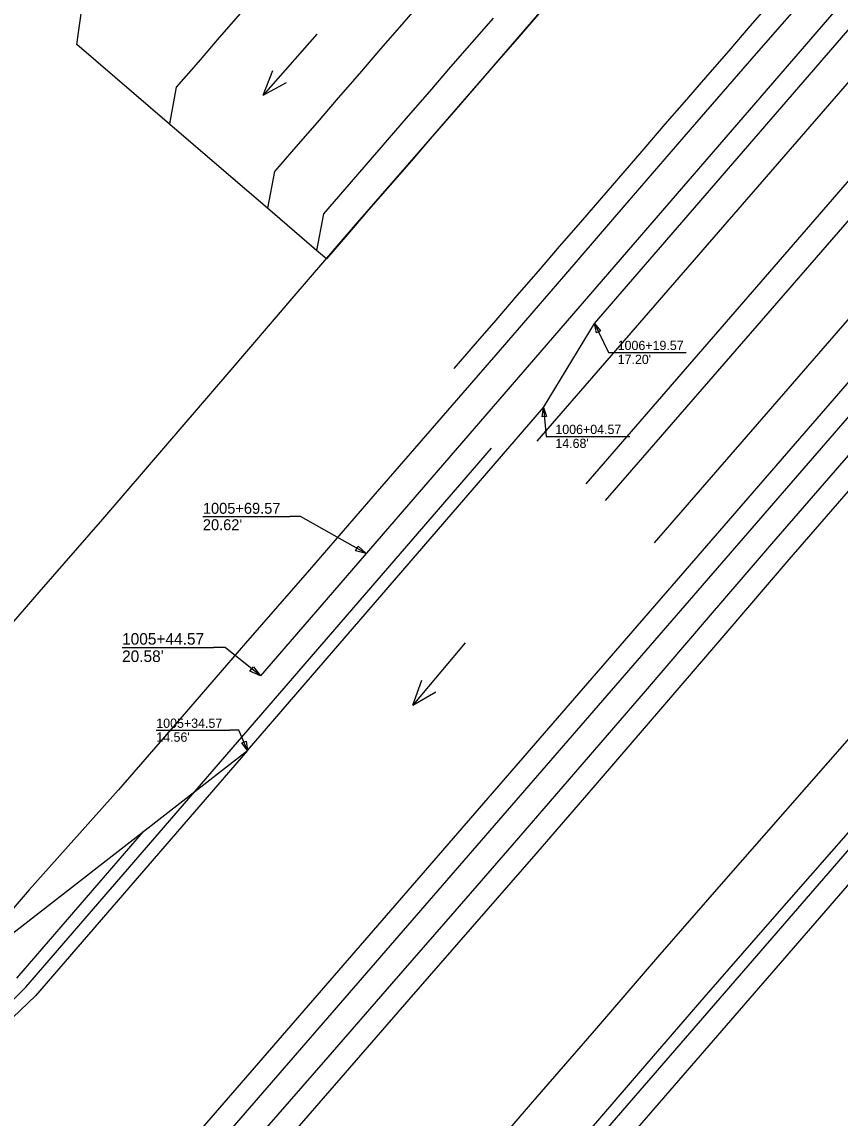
# Model space of a CAD drawing. Extents: x 1006695 to 1009377, y 1883329 to 1886115.
# Drawn here: x 1007700.6 to 1007827, y 1884510 to 1884679.4 of the extents above; entities that cross this region are included whole.
import ezdxf

# ---------------------------------------------------------------- set-up
doc = ezdxf.new("R2010")
doc.units = 0
for name, color, linetype in [('R_Drainage Concrete Lining I-30', 7, 'Continuous'), ('R_I-30 Information', 7, 'Continuous'), ('R_No Plot', 7, 'Continuous'), ('R_Prop EOL', 7, 'Continuous'), ('R_Prop EOS I-30', 7, 'Continuous'), ('R_Prop Fence', 7, 'Continuous'), ('R_Prop I-30 Guardrail', 7, 'Continuous'), ('R_Water Annot', 7, 'Continuous')]:
    doc.layers.add(name, color=color, linetype=linetype)

msp = doc.modelspace()

# ---------------------------------------------------------------- linework, layer by layer
at = {"layer": 'R_Drainage Concrete Lining I-30'}
for p, q in [((1007735.45, 1884566.81), (1007702.68, 1884528.85)), ((1007719.32, 1884554.25), (1007699.75, 1884531.58)), ((1007702.68, 1884528.85), (1007666.48, 1884494.25))]:
    msp.add_line(p, q, dxfattribs=at)
at = {"layer": 'R_I-30 Information'}
for p, q in [((1007780.22, 1884614.59), (1007976.64, 1884841.35)), ((1007787.78, 1884608.04), (1007984.2, 1884834.8)), ((1007790.8, 1884605.42), (1007987.22, 1884832.18)), ((1007798.36, 1884598.88), (1007994.78, 1884825.63))]:
    msp.add_line(p, q, dxfattribs=at)
for points in [[(1007740.78, 1884505.63), (1007750.62, 1884516.95), (1007760.46, 1884528.27), (1007770.23, 1884539.51), (1007780.07, 1884550.83), (1007789.88, 1884562.17), (1007799.65, 1884573.56), (1007809.41, 1884584.94), (1007819.18, 1884596.32), (1007829.02, 1884607.64), (1007838.86, 1884618.96), (1007848.7, 1884630.28), (1007858.47, 1884641.66), (1007868.2, 1884653.07), (1007887.67, 1884675.88), (1007897.62, 1884687.1)], [(1007693.41, 1884579.94), (1007703.26, 1884591.25), (1007713.1, 1884602.57), (1007722.86, 1884613.89), (1007732.62, 1884625.27), (1007742.38, 1884636.66), (1007752.15, 1884648.04), (1007761.98, 1884659.36), (1007771.8, 1884670.7), (1007781.63, 1884682.03)], [(1007780.39, 1884680.59), (1007777.11, 1884676.82), (1007773.84, 1884673.04), (1007770.56, 1884669.26), (1007767.28, 1884665.48), (1007764.01, 1884661.71), (1007760.73, 1884657.93), (1007757.46, 1884654.15), (1007754.18, 1884650.37), (1007750.91, 1884646.59), (1007747.65, 1884642.8), (1007747.65, 1884642.8), (1007746.14, 1884644.1), (1007744.62, 1884645.4), (1007738.55, 1884650.62), (1007731.82, 1884656.4), (1007723.38, 1884663.65), (1007709.06, 1884675.96), (1007709.06, 1884675.97), (1007709.92, 1884681.82)], [(1007762.57, 1884682.81), (1007759.3, 1884679.03), (1007756.03, 1884675.25), (1007752.75, 1884671.47), (1007749.48, 1884667.69), (1007746.21, 1884663.91), (1007742.93, 1884660.13), (1007739.61, 1884656.3), (1007738.55, 1884650.62), (1007738.55, 1884650.62)], [(1007816.39, 1884682.53), (1007813.11, 1884678.76), (1007809.84, 1884674.98), (1007806.56, 1884671.21), (1007803.29, 1884667.43), (1007799.97, 1884663.61), (1007796.71, 1884659.82), (1007793.44, 1884656.04), (1007790.17, 1884652.26), (1007786.9, 1884648.47), (1007783.63, 1884644.69), (1007780.36, 1884640.91), (1007777.09, 1884637.12), (1007773.82, 1884633.34), (1007770.63, 1884629.65), (1007767.36, 1884625.87), (1007767.35, 1884625.86)], [(1007769.41, 1884500.69), (1007779.21, 1884512.04), (1007789.07, 1884523.47), (1007798.87, 1884534.82), (1007808.73, 1884546.12), (1007818.61, 1884557.41), (1007828.48, 1884568.7), (1007838.31, 1884580.03), (1007848.08, 1884591.4), (1007857.85, 1884602.78), (1007867.63, 1884614.15), (1007877.53, 1884625.42), (1007887.41, 1884636.7), (1007906.97, 1884659.44), (1007916.75, 1884670.81), (1007926.47, 1884682.23)], [(1007734.37, 1884680.79), (1007731.1, 1884677.01), (1007727.82, 1884673.23), (1007724.45, 1884669.34), (1007723.38, 1884663.66), (1007723.38, 1884663.65)], [(1007773.4, 1884680.03), (1007770.13, 1884676.25), (1007766.85, 1884672.47), (1007763.58, 1884668.69), (1007760.31, 1884664.92), (1007757.03, 1884661.14), (1007753.76, 1884657.36), (1007750.49, 1884653.58), (1007747.2, 1884649.78), (1007746.14, 1884644.1), (1007746.14, 1884644.1)]]:
    msp.add_lwpolyline(points, dxfattribs=at)
at = {"layer": 'R_No Plot'}
for p, q in [((1007792.66, 1884628.34), (1007803.26, 1884628.34)), ((1007783.03, 1884615.36), (1007794.56, 1884615.36)), ((1007728.56, 1884602.96), (1007741.98, 1884602.96)), ((1007716.07, 1884582.71), (1007730.19, 1884582.71)), ((1007721.36, 1884569.93), (1007732.71, 1884569.93))]:
    msp.add_line(p, q, dxfattribs=at)
for points in [[(1007789.1, 1884632.79), (1007791.23, 1884628.34), (1007792.66, 1884628.34)], [(1007781.18, 1884619.8), (1007781.59, 1884615.36), (1007783.03, 1884615.36)], [(1007753.78, 1884597.23), (1007743.67, 1884602.96), (1007741.98, 1884602.96)], [(1007737.44, 1884578.31), (1007731.98, 1884582.71), (1007730.19, 1884582.71)], [(1007735.44, 1884566.81), (1007734.14, 1884569.93), (1007732.71, 1884569.93)]]:
    msp.add_lwpolyline(points, dxfattribs=at)
for points in [[(1007789.1, 1884632.79), (1007790.01, 1884631.68), (1007789.38, 1884631.38)], [(1007781.18, 1884619.8), (1007781.66, 1884618.44), (1007780.97, 1884618.38)], [(1007753.78, 1884597.23), (1007752.15, 1884597.68), (1007752.56, 1884598.4)], [(1007737.44, 1884578.31), (1007735.82, 1884579.06), (1007736.37, 1884579.73)], [(1007735.44, 1884566.81), (1007734.59, 1884567.96), (1007735.23, 1884568.23)]]:
    msp.add_lwpolyline(points, close=True, dxfattribs=at)
at = {"layer": 'R_Prop EOL'}
for radius, start in [(1443.39, 37.04506), (1421.39, 35.65164)]:
    msp.add_arc((1006901.08, 1883681.49), radius, start, 53.47197, dxfattribs=at)
at = {"layer": 'R_Prop EOS I-30'}
for p, q in [((1007789.1, 1884632.79), (1008066.81, 1884954.51)), ((1007648.59, 1884416.23), (1007989.05, 1884809.28)), ((1007713.67, 1884413.61), (1007972.2, 1884712.26)), ((1007781.18, 1884619.8), (1007789.1, 1884632.79)), ((1007735.44, 1884566.81), (1007781.18, 1884619.8))]:
    msp.add_line(p, q, dxfattribs=at)
for points in [[(1007786.4, 1884505.84), (1007796.26, 1884517.26), (1007806.04, 1884528.59), (1007815.89, 1884539.87), (1007825.76, 1884551.15), (1007835.65, 1884562.46), (1007845.5, 1884573.82), (1007855.29, 1884585.22), (1007865.05, 1884596.59), (1007874.8, 1884607.91), (1007884.67, 1884619.16), (1007894.58, 1884630.47), (1007914.18, 1884653.24), (1007923.97, 1884664.63), (1007933.68, 1884676.05), (1007943.28, 1884687.18), (1007953.08, 1884698.54), (1007962.87, 1884709.9), (1007972.64, 1884721.22), (1007988.72, 1884741.6)], [(1007738.1, 1884508.07), (1007747.94, 1884519.39), (1007757.78, 1884530.72), (1007767.55, 1884541.96), (1007777.38, 1884553.27), (1007787.19, 1884564.6), (1007796.95, 1884575.97), (1007806.71, 1884587.36), (1007816.49, 1884598.75), (1007826.34, 1884610.09), (1007836.18, 1884621.4), (1007846.01, 1884632.7), (1007855.77, 1884644.07), (1007865.5, 1884655.48), (1007884.99, 1884678.32), (1007894.96, 1884689.56)], [(1007823.56, 1884685.45), (1007813.72, 1884674.12), (1007803.89, 1884662.79), (1007794.09, 1884651.45), (1007784.29, 1884640.09), (1007774.48, 1884628.75), (1007764.66, 1884617.41), (1007754.84, 1884606.07), (1007745.02, 1884594.73), (1007735.17, 1884583.36), (1007725.34, 1884572.03), (1007715.52, 1884560.7), (1007701.7, 1884545.25)], [(1007695.44, 1884537.96), (1007696.84, 1884536.74), (1007735.44, 1884566.81)], [(1007701.7, 1884545.25), (1007695.44, 1884537.96)]]:
    msp.add_lwpolyline(points, dxfattribs=at)
at = {"layer": 'R_Prop Fence'}
msp.add_lwpolyline([(1007665.72, 1884494.91), (1007701.21, 1884530.22), (1007773.14, 1884613.54)], dxfattribs=at)
at = {"layer": 'R_Prop I-30 Guardrail'}
for p, q in [((1008113.17, 1885013.57), (1007737.44, 1884578.31)), ((1007657.79, 1884421.5), (1007985.15, 1884799.43)), ((1007717.57, 1884423.47), (1007963.01, 1884706.99))]:
    msp.add_line(p, q, dxfattribs=at)
at = {"layer": 'R_Water Annot'}
for p, q in [((1007746.17, 1884677.56), (1007737.88, 1884668.11)), ((1007737.88, 1884668.11), (1007739.37, 1884671.92)), ((1007737.88, 1884668.11), (1007741.47, 1884670.08)), ((1007769.07, 1884583.42), (1007761, 1884573.79)), ((1007761, 1884573.79), (1007762.4, 1884577.64)), ((1007761, 1884573.79), (1007764.54, 1884575.84))]:
    msp.add_line(p, q, dxfattribs=at)

# ---------------------------------------------------------------- texts
at = {"layer": 'R_No Plot'}
for s, height, p in [('1006+19.57', 1.436, (1007792.66, 1884628.7)), ("17.20'", 1.436, (1007792.66, 1884626.54)), ('1006+04.57', 1.436, (1007783.03, 1884615.72)), ("14.68'", 1.436, (1007783.03, 1884613.56)), ('1005+44.57', 1.786, (1007716.07, 1884583.15)), ("20.58'", 1.786, (1007716.07, 1884580.47))]:
    msp.add_text(s, height=height, dxfattribs=at).set_placement(p)
for s, height, p in [('1005+69.57', 1.688, (1007728.56, 1884603.39)), ("20.62'", 1.688, (1007728.56, 1884600.85)), ('1005+34.57', 1.436, (1007721.36, 1884570.29)), ("14.56'", 1.436, (1007721.36, 1884568.14))]:
    msp.add_text(s, height=height, rotation=360, dxfattribs=at).set_placement(p)

doc.saveas('drawing.dxf')
